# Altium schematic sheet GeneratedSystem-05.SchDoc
size 150 x 80 mm
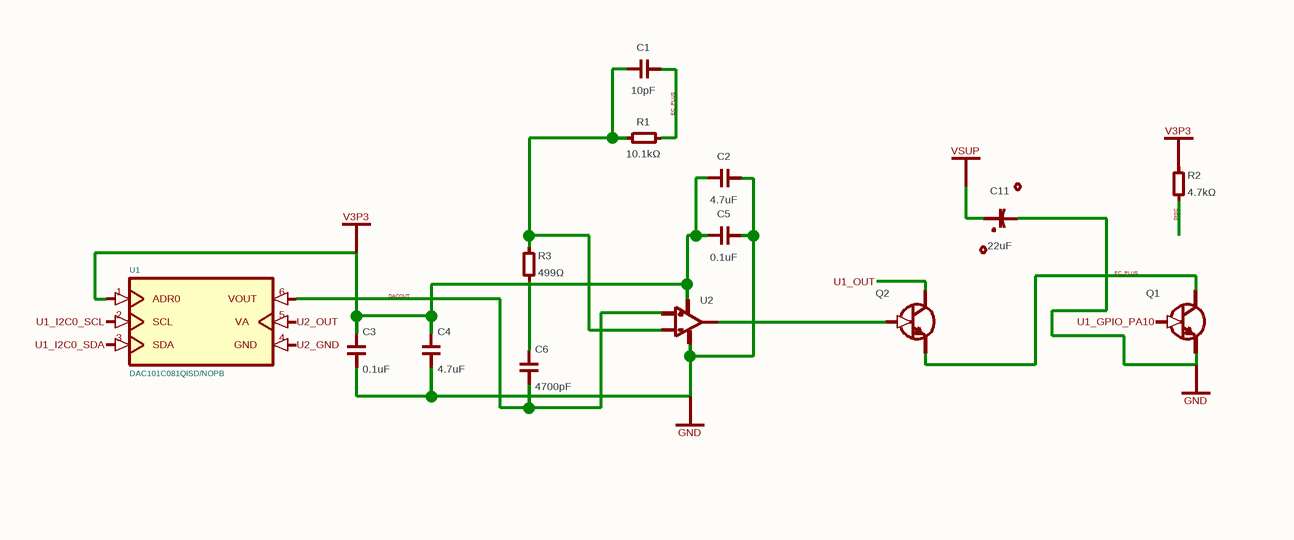
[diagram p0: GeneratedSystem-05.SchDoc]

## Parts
C1  10pF
C2  4.7uF
C3  0.1uF
C4  4.7uF
C5  0.1uF
C6  4700pF
C11  22uF
Q1  (no value)
Q2  (no value)
R1  10.1kΩ
R2  4.7kΩ
R3  499Ω
U1  (no value)
U2  (no value)

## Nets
GND: C2.2(neg) C3.2(cathode) C4.2(cathode) C5.2(neg) C11.2(neg) Q1.3(emitter) U2.3(V-)
V3P3: C2.1(pos) C3.1(anode) C4.1(anode) C5.1(pos) R2.1(anode) U1.1(ADR0) U2.5(V+)
VSUP: C11.1(pos)
U1_GPIO_PA10: Q1.2(base)
U1_I2C0_SCL: U1.2(SCL)
U1_I2C0_SDA: U1.3(SDA)
U1_OUT: Q2.1(collector)
U2_GND: U1.4(GND)
U2_OUT: U1.5(VA)
NetC1_1: C1.1(pos) R1.2(cathode)
NetC1_2: C1.2(neg) R1.1(anode) R3.1(anode) U2.2(inp2)
NetC6_1: C6.1(anode) R3.2(cathode)
NetC6_2: C6.2(cathode) U1.6(VOUT) U2.1(inp1)
NetQ1_1: Q1.1(collector) Q2.3(emitter)
NetQ2_2: Q2.2(base) U2.4(out)

Not connected (* = marked no-connect by the designer): R2 2(cathode)

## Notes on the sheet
- EC_PLUS
- DACOUT
- (near R2) DISC

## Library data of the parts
C1 = capacitor_left
C2 C5 = capacitor_right
C3 C4 C6 = capacitor_down
C11 = capacitor_polarized_right
Q1 Q2 = npn_bipolar_transistor_down
R1 = boxresistor_right
R2 R3 = boxresistor_down
U1 = U1
U2 = opamp_with_power_right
